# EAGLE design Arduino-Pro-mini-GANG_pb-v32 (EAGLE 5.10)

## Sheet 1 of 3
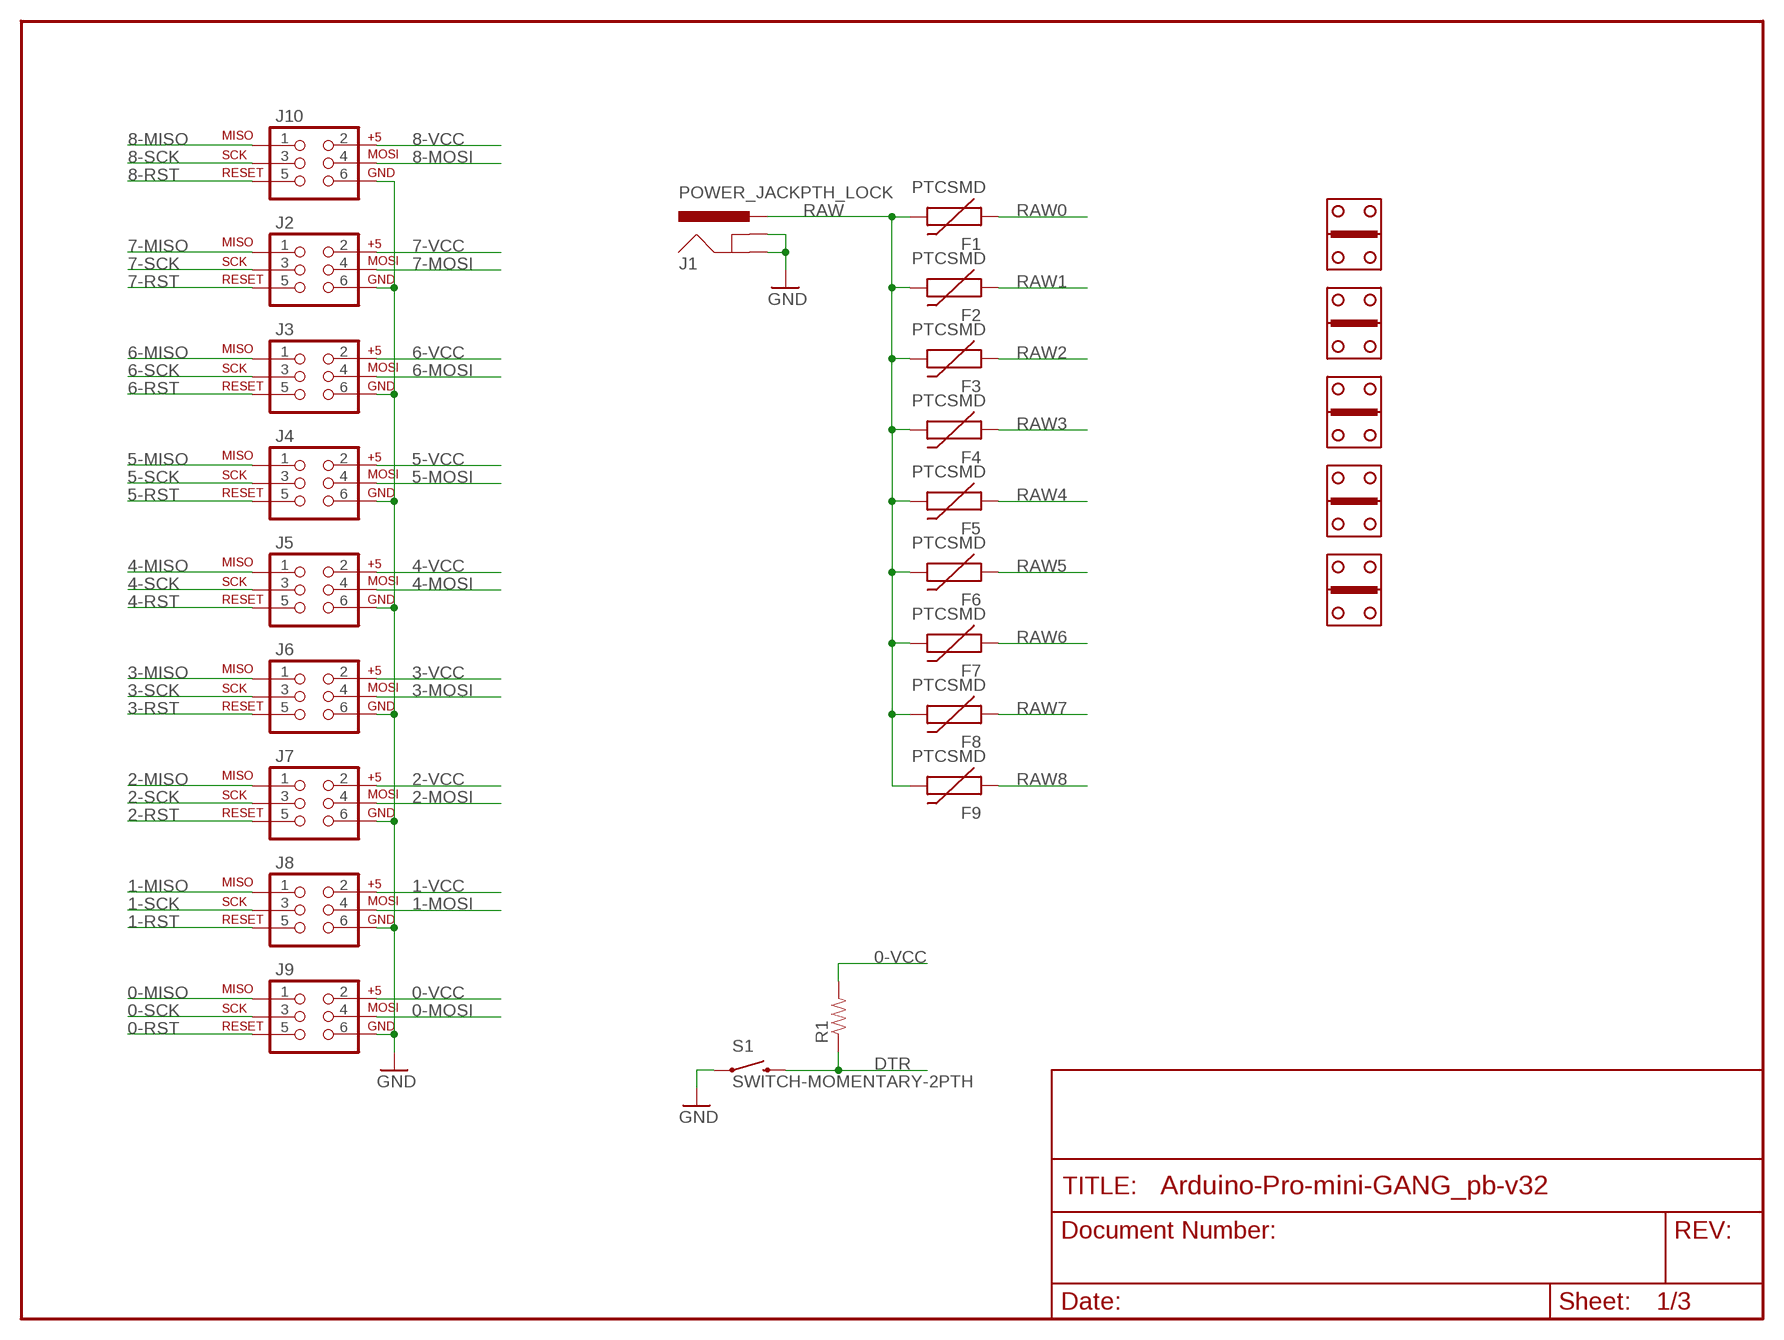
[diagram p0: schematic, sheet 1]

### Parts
F1  PTCSMD  [PTC-1206]
F2  PTCSMD  [PTC-1206]
F3  PTCSMD  [PTC-1206]
F4  PTCSMD  [PTC-1206]
F5  PTCSMD  [PTC-1206]
F6  PTCSMD  [PTC-1206]
F7  PTCSMD  [PTC-1206]
F8  PTCSMD  [PTC-1206]
F9  PTCSMD  [PTC-1206]
J1  POWER_JACKPTH_LOCK  [POWER_JACK_PTH_LOCK]
J2  AVR_SPI_PRG_62X3_LOCK  [2X3_LOCK]
J3  AVR_SPI_PRG_62X3_LOCK  [2X3_LOCK]
J4  AVR_SPI_PRG_62X3_LOCK  [2X3_LOCK]
J5  AVR_SPI_PRG_62X3_LOCK  [2X3_LOCK]
J6  AVR_SPI_PRG_62X3_LOCK  [2X3_LOCK]
J7  AVR_SPI_PRG_62X3_LOCK  [2X3_LOCK]
J8  AVR_SPI_PRG_62X3_LOCK  [2X3_LOCK]
J9  AVR_SPI_PRG_62X3_LOCK  [2X3_LOCK]
J10  AVR_SPI_PRG_62X3_LOCK  [2X3_LOCK]
R1  RESISTOR0603-RES  [0603-RES]
S1  SWITCH-MOMENTARY-2PTH  [TACTILE-PTH]
U$4  GOLD_HINDGESTANDARD  [GOLD_HINDGE]
U$5  GOLD_HINDGESTANDARD  [GOLD_HINDGE]
U$6  GOLD_HINDGESTANDARD  [GOLD_HINDGE]
U$7  GOLD_HINDGESTANDARD  [GOLD_HINDGE]
U$8  GOLD_HINDGESTANDARD  [GOLD_HINDGE]

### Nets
0-MISO: J9.1 ; also sheet 2
0-MOSI: J9.4 ; also sheet 2
0-RST: J9.5 ; also sheet 2
0-SCK: J9.3 ; also sheet 2
0-VCC: J9.2 R1.2 ; also sheet 2
1-MISO: J8.1 ; also sheet 2
1-MOSI: J8.4 ; also sheet 2
1-RST: J8.5 ; also sheet 2
1-SCK: J8.3 ; also sheet 2
1-VCC: J8.2 ; also sheet 2
2-MISO: J7.1 ; also sheet 2
2-MOSI: J7.4 ; also sheet 2
2-RST: J7.5 ; also sheet 2
2-SCK: J7.3 ; also sheet 2
2-VCC: J7.2 ; also sheet 2
3-MISO: J6.1 ; also sheet 2
3-MOSI: J6.4 ; also sheet 2
3-RST: J6.5 ; also sheet 2
3-SCK: J6.3 ; also sheet 2
3-VCC: J6.2 ; also sheet 2
4-MISO: J5.1 ; also sheet 2
4-MOSI: J5.4 ; also sheet 2
4-RST: J5.5 ; also sheet 2
4-SCK: J5.3 ; also sheet 2
4-VCC: J5.2 ; also sheet 2
5-MISO: J4.1 ; also sheet 2
5-MOSI: J4.4 ; also sheet 2
5-RST: J4.5 ; also sheet 2
5-SCK: J4.3 ; also sheet 2
5-VCC: J4.2 ; also sheet 2
6-MISO: J3.1 ; also sheet 2
6-MOSI: J3.4 ; also sheet 2
6-RST: J3.5 ; also sheet 2
6-SCK: J3.3 ; also sheet 2
6-VCC: J3.2 ; also sheet 2
7-MISO: J2.1 ; also sheet 2
7-MOSI: J2.4 ; also sheet 2
7-RST: J2.5 ; also sheet 2
7-SCK: J2.3 ; also sheet 2
7-VCC: J2.2 ; also sheet 2
8-MISO: J10.1 ; also sheet 2
8-MOSI: J10.4 ; also sheet 2
8-RST: J10.5 ; also sheet 2
8-SCK: J10.3 ; also sheet 2
8-VCC: J10.2 ; also sheet 2
DTR: R1.1 S1.3 ; also sheet 2
GND: J1.GND J1.GNDBREAK J2.6 J3.6 J4.6 J5.6 J6.6 J7.6 J8.6 J9.6 J10.6 S1.1 ; also sheet 2
RAW: F1.2 F2.2 F3.2 F4.2 F5.2 F6.2 F7.2 F8.2 F9.2 J1.PWR
RAW0: F1.1 ; also sheet 2
RAW1: F2.1 ; also sheet 2
RAW2: F3.1 ; also sheet 2
RAW3: F4.1 ; also sheet 2
RAW4: F5.1 ; also sheet 2
RAW5: F6.1 ; also sheet 2
RAW6: F7.1 ; also sheet 2
RAW7: F8.1 ; also sheet 2
RAW8: F9.1 ; also sheet 2

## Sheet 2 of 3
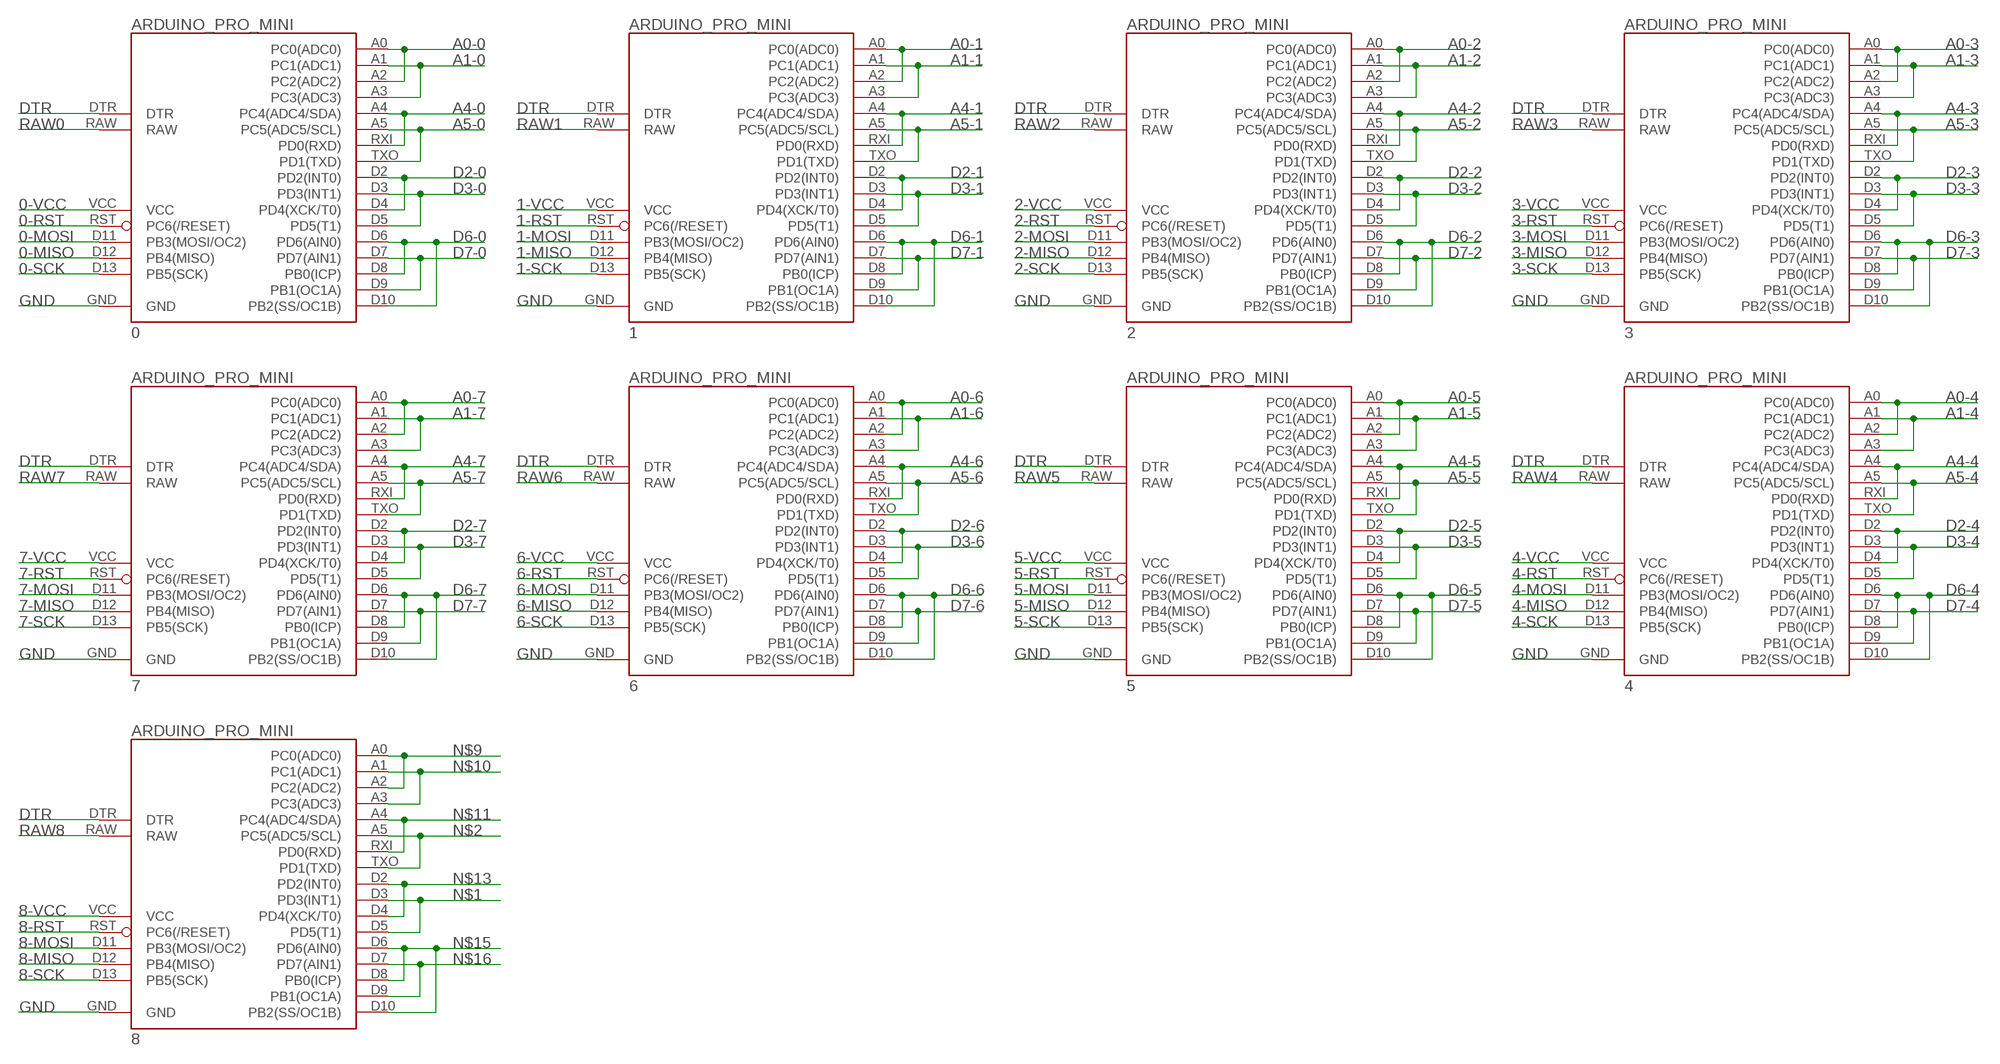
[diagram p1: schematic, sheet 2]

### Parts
0  ARDUINO_PRO_MINI  [ARDUINO_PRO_MINI]
1  ARDUINO_PRO_MINI  [ARDUINO_PRO_MINI]
2  ARDUINO_PRO_MINI  [ARDUINO_PRO_MINI]
3  ARDUINO_PRO_MINI  [ARDUINO_PRO_MINI]
4  ARDUINO_PRO_MINI  [ARDUINO_PRO_MINI]
5  ARDUINO_PRO_MINI  [ARDUINO_PRO_MINI]
6  ARDUINO_PRO_MINI  [ARDUINO_PRO_MINI]
7  ARDUINO_PRO_MINI  [ARDUINO_PRO_MINI]
8  ARDUINO_PRO_MINI  [ARDUINO_PRO_MINI]

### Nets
0-MISO: 0.D12(PB4(MISO)) ; also sheet 1
0-MOSI: 0.D11(PB3(MOSI/OC2)) ; also sheet 1
0-RST: 0.RST(PC6(/RESET)) ; also sheet 1
0-SCK: 0.D13(PB5(SCK)) ; also sheet 1
0-VCC: 0.VCC ; also sheet 1
1-MISO: 1.D12(PB4(MISO)) ; also sheet 1
1-MOSI: 1.D11(PB3(MOSI/OC2)) ; also sheet 1
1-RST: 1.RST(PC6(/RESET)) ; also sheet 1
1-SCK: 1.D13(PB5(SCK)) ; also sheet 1
1-VCC: 1.VCC ; also sheet 1
2-MISO: 2.D12(PB4(MISO)) ; also sheet 1
2-MOSI: 2.D11(PB3(MOSI/OC2)) ; also sheet 1
2-RST: 2.RST(PC6(/RESET)) ; also sheet 1
2-SCK: 2.D13(PB5(SCK)) ; also sheet 1
2-VCC: 2.VCC ; also sheet 1
3-MISO: 3.D12(PB4(MISO)) ; also sheet 1
3-MOSI: 3.D11(PB3(MOSI/OC2)) ; also sheet 1
3-RST: 3.RST(PC6(/RESET)) ; also sheet 1
3-SCK: 3.D13(PB5(SCK)) ; also sheet 1
3-VCC: 3.VCC ; also sheet 1
4-MISO: 4.D12(PB4(MISO)) ; also sheet 1
4-MOSI: 4.D11(PB3(MOSI/OC2)) ; also sheet 1
4-RST: 4.RST(PC6(/RESET)) ; also sheet 1
4-SCK: 4.D13(PB5(SCK)) ; also sheet 1
4-VCC: 4.VCC ; also sheet 1
5-MISO: 5.D12(PB4(MISO)) ; also sheet 1
5-MOSI: 5.D11(PB3(MOSI/OC2)) ; also sheet 1
5-RST: 5.RST(PC6(/RESET)) ; also sheet 1
5-SCK: 5.D13(PB5(SCK)) ; also sheet 1
5-VCC: 5.VCC ; also sheet 1
6-MISO: 6.D12(PB4(MISO)) ; also sheet 1
6-MOSI: 6.D11(PB3(MOSI/OC2)) ; also sheet 1
6-RST: 6.RST(PC6(/RESET)) ; also sheet 1
6-SCK: 6.D13(PB5(SCK)) ; also sheet 1
6-VCC: 6.VCC ; also sheet 1
7-MISO: 7.D12(PB4(MISO)) ; also sheet 1
7-MOSI: 7.D11(PB3(MOSI/OC2)) ; also sheet 1
7-RST: 7.RST(PC6(/RESET)) ; also sheet 1
7-SCK: 7.D13(PB5(SCK)) ; also sheet 1
7-VCC: 7.VCC ; also sheet 1
8-MISO: 8.D12(PB4(MISO)) ; also sheet 1
8-MOSI: 8.D11(PB3(MOSI/OC2)) ; also sheet 1
8-RST: 8.RST(PC6(/RESET)) ; also sheet 1
8-SCK: 8.D13(PB5(SCK)) ; also sheet 1
8-VCC: 8.VCC ; also sheet 1
A0-0: 0.A0(PC0(ADC0)) 0.A2(PC2(ADC2))
A0-1: 1.A0(PC0(ADC0)) 1.A2(PC2(ADC2))
A0-2: 2.A0(PC0(ADC0)) 2.A2(PC2(ADC2))
A0-3: 3.A0(PC0(ADC0)) 3.A2(PC2(ADC2))
A0-4: 4.A0(PC0(ADC0)) 4.A2(PC2(ADC2))
A0-5: 5.A0(PC0(ADC0)) 5.A2(PC2(ADC2))
A0-6: 6.A0(PC0(ADC0)) 6.A2(PC2(ADC2))
A0-7: 7.A0(PC0(ADC0)) 7.A2(PC2(ADC2))
A1-0: 0.A1(PC1(ADC1)) 0.A3(PC3(ADC3))
A1-1: 1.A1(PC1(ADC1)) 1.A3(PC3(ADC3))
A1-2: 2.A1(PC1(ADC1)) 2.A3(PC3(ADC3))
A1-3: 3.A1(PC1(ADC1)) 3.A3(PC3(ADC3))
A1-4: 4.A1(PC1(ADC1)) 4.A3(PC3(ADC3))
A1-5: 5.A1(PC1(ADC1)) 5.A3(PC3(ADC3))
A1-6: 6.A1(PC1(ADC1)) 6.A3(PC3(ADC3))
A1-7: 7.A1(PC1(ADC1)) 7.A3(PC3(ADC3))
A4-0: 0.A4(PC4(ADC4/SDA)) 0.RXI(PD0(RXD))
A4-1: 1.A4(PC4(ADC4/SDA)) 1.RXI(PD0(RXD))
A4-2: 2.A4(PC4(ADC4/SDA)) 2.RXI(PD0(RXD))
A4-3: 3.A4(PC4(ADC4/SDA)) 3.RXI(PD0(RXD))
A4-4: 4.A4(PC4(ADC4/SDA)) 4.RXI(PD0(RXD))
A4-5: 5.A4(PC4(ADC4/SDA)) 5.RXI(PD0(RXD))
A4-6: 6.A4(PC4(ADC4/SDA)) 6.RXI(PD0(RXD))
A4-7: 7.A4(PC4(ADC4/SDA)) 7.RXI(PD0(RXD))
A5-0: 0.A5(PC5(ADC5/SCL)) 0.TXO(PD1(TXD))
A5-1: 1.A5(PC5(ADC5/SCL)) 1.TXO(PD1(TXD))
A5-2: 2.A5(PC5(ADC5/SCL)) 2.TXO(PD1(TXD))
A5-3: 3.A5(PC5(ADC5/SCL)) 3.TXO(PD1(TXD))
A5-4: 4.A5(PC5(ADC5/SCL)) 4.TXO(PD1(TXD))
A5-5: 5.A5(PC5(ADC5/SCL)) 5.TXO(PD1(TXD))
A5-6: 6.A5(PC5(ADC5/SCL)) 6.TXO(PD1(TXD))
A5-7: 7.A5(PC5(ADC5/SCL)) 7.TXO(PD1(TXD))
D2-0: 0.D2(PD2(INT0)) 0.D4(PD4(XCK/T0))
D2-1: 1.D2(PD2(INT0)) 1.D4(PD4(XCK/T0))
D2-2: 2.D2(PD2(INT0)) 2.D4(PD4(XCK/T0))
D2-3: 3.D2(PD2(INT0)) 3.D4(PD4(XCK/T0))
D2-4: 4.D2(PD2(INT0)) 4.D4(PD4(XCK/T0))
D2-5: 5.D2(PD2(INT0)) 5.D4(PD4(XCK/T0))
D2-6: 6.D2(PD2(INT0)) 6.D4(PD4(XCK/T0))
D2-7: 7.D2(PD2(INT0)) 7.D4(PD4(XCK/T0))
D3-0: 0.D3(PD3(INT1)) 0.D5(PD5(T1))
D3-1: 1.D3(PD3(INT1)) 1.D5(PD5(T1))
D3-2: 2.D3(PD3(INT1)) 2.D5(PD5(T1))
D3-3: 3.D3(PD3(INT1)) 3.D5(PD5(T1))
D3-4: 4.D3(PD3(INT1)) 4.D5(PD5(T1))
D3-5: 5.D3(PD3(INT1)) 5.D5(PD5(T1))
D3-6: 6.D3(PD3(INT1)) 6.D5(PD5(T1))
D3-7: 7.D3(PD3(INT1)) 7.D5(PD5(T1))
D6-0: 0.D6(PD6(AIN0)) 0.D8(PB0(ICP)) 0.D10(PB2(SS/OC1B))
D6-1: 1.D6(PD6(AIN0)) 1.D8(PB0(ICP)) 1.D10(PB2(SS/OC1B))
D6-2: 2.D6(PD6(AIN0)) 2.D8(PB0(ICP)) 2.D10(PB2(SS/OC1B))
D6-3: 3.D6(PD6(AIN0)) 3.D8(PB0(ICP)) 3.D10(PB2(SS/OC1B))
D6-4: 4.D6(PD6(AIN0)) 4.D8(PB0(ICP)) 4.D10(PB2(SS/OC1B))
D6-5: 5.D6(PD6(AIN0)) 5.D8(PB0(ICP)) 5.D10(PB2(SS/OC1B))
D6-6: 6.D6(PD6(AIN0)) 6.D8(PB0(ICP)) 6.D10(PB2(SS/OC1B))
D6-7: 7.D6(PD6(AIN0)) 7.D8(PB0(ICP)) 7.D10(PB2(SS/OC1B))
D7-0: 0.D7(PD7(AIN1)) 0.D9(PB1(OC1A))
D7-1: 1.D7(PD7(AIN1)) 1.D9(PB1(OC1A))
D7-2: 2.D7(PD7(AIN1)) 2.D9(PB1(OC1A))
D7-3: 3.D7(PD7(AIN1)) 3.D9(PB1(OC1A))
D7-4: 4.D7(PD7(AIN1)) 4.D9(PB1(OC1A))
D7-5: 5.D7(PD7(AIN1)) 5.D9(PB1(OC1A))
D7-6: 6.D7(PD7(AIN1)) 6.D9(PB1(OC1A))
D7-7: 7.D7(PD7(AIN1)) 7.D9(PB1(OC1A))
DTR: 0.DTR 1.DTR 2.DTR 3.DTR 4.DTR 5.DTR 6.DTR 7.DTR 8.DTR ; also sheet 1
GND: 0.GND 1.GND 2.GND 3.GND 4.GND 5.GND 6.GND 7.GND 8.GND ; also sheet 1
N$1: 8.D3(PD3(INT1)) 8.D5(PD5(T1))
N$2: 8.A5(PC5(ADC5/SCL)) 8.TXO(PD1(TXD))
N$9: 8.A0(PC0(ADC0)) 8.A2(PC2(ADC2))
N$10: 8.A1(PC1(ADC1)) 8.A3(PC3(ADC3))
N$11: 8.A4(PC4(ADC4/SDA)) 8.RXI(PD0(RXD))
N$13: 8.D2(PD2(INT0)) 8.D4(PD4(XCK/T0))
N$15: 8.D6(PD6(AIN0)) 8.D8(PB0(ICP)) 8.D10(PB2(SS/OC1B))
N$16: 8.D7(PD7(AIN1)) 8.D9(PB1(OC1A))
RAW0: 0.RAW ; also sheet 1
RAW1: 1.RAW ; also sheet 1
RAW2: 2.RAW ; also sheet 1
RAW3: 3.RAW ; also sheet 1
RAW4: 4.RAW ; also sheet 1
RAW5: 5.RAW ; also sheet 1
RAW6: 6.RAW ; also sheet 1
RAW7: 7.RAW ; also sheet 1
RAW8: 8.RAW ; also sheet 1

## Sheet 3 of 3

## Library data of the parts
0 1-8 = unclepetes:ARDUINO_PRO_MINI
F1-F9 = SparkFun:PTC: Resettable Fuse PTC
J1 = SparkFun:POWER_JACK: Power Jack This is the standard 5.5mm barrel jack for power. The PTH is the most common, proven, reliable, footprint. All others are experimental. The Slot footprint only works if the mill layer is transmitted to the PCB fab house so be warned. Spark Fun Electronics SKU : PRT-00119. Mating wall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
J2-J10 = Testing:AVR_SPI_PRG_6: AVR ISP 6 Pin This is the reduced ISP connector for AVR programming. Common on Arduino. This footprint will take up less PCB space and can be used with a 10-pin to 6-pin adapter such as SKU: BOB-08508
R1 = SparkFun:RESISTOR: Resistor
S1 = SparkFun:SWITCH-MOMENTARY-2
U$4-U$8 = Testing:GOLD_HINDGE

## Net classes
0 Default: width 0.203 mm
1 VCC: width 0.305 mm

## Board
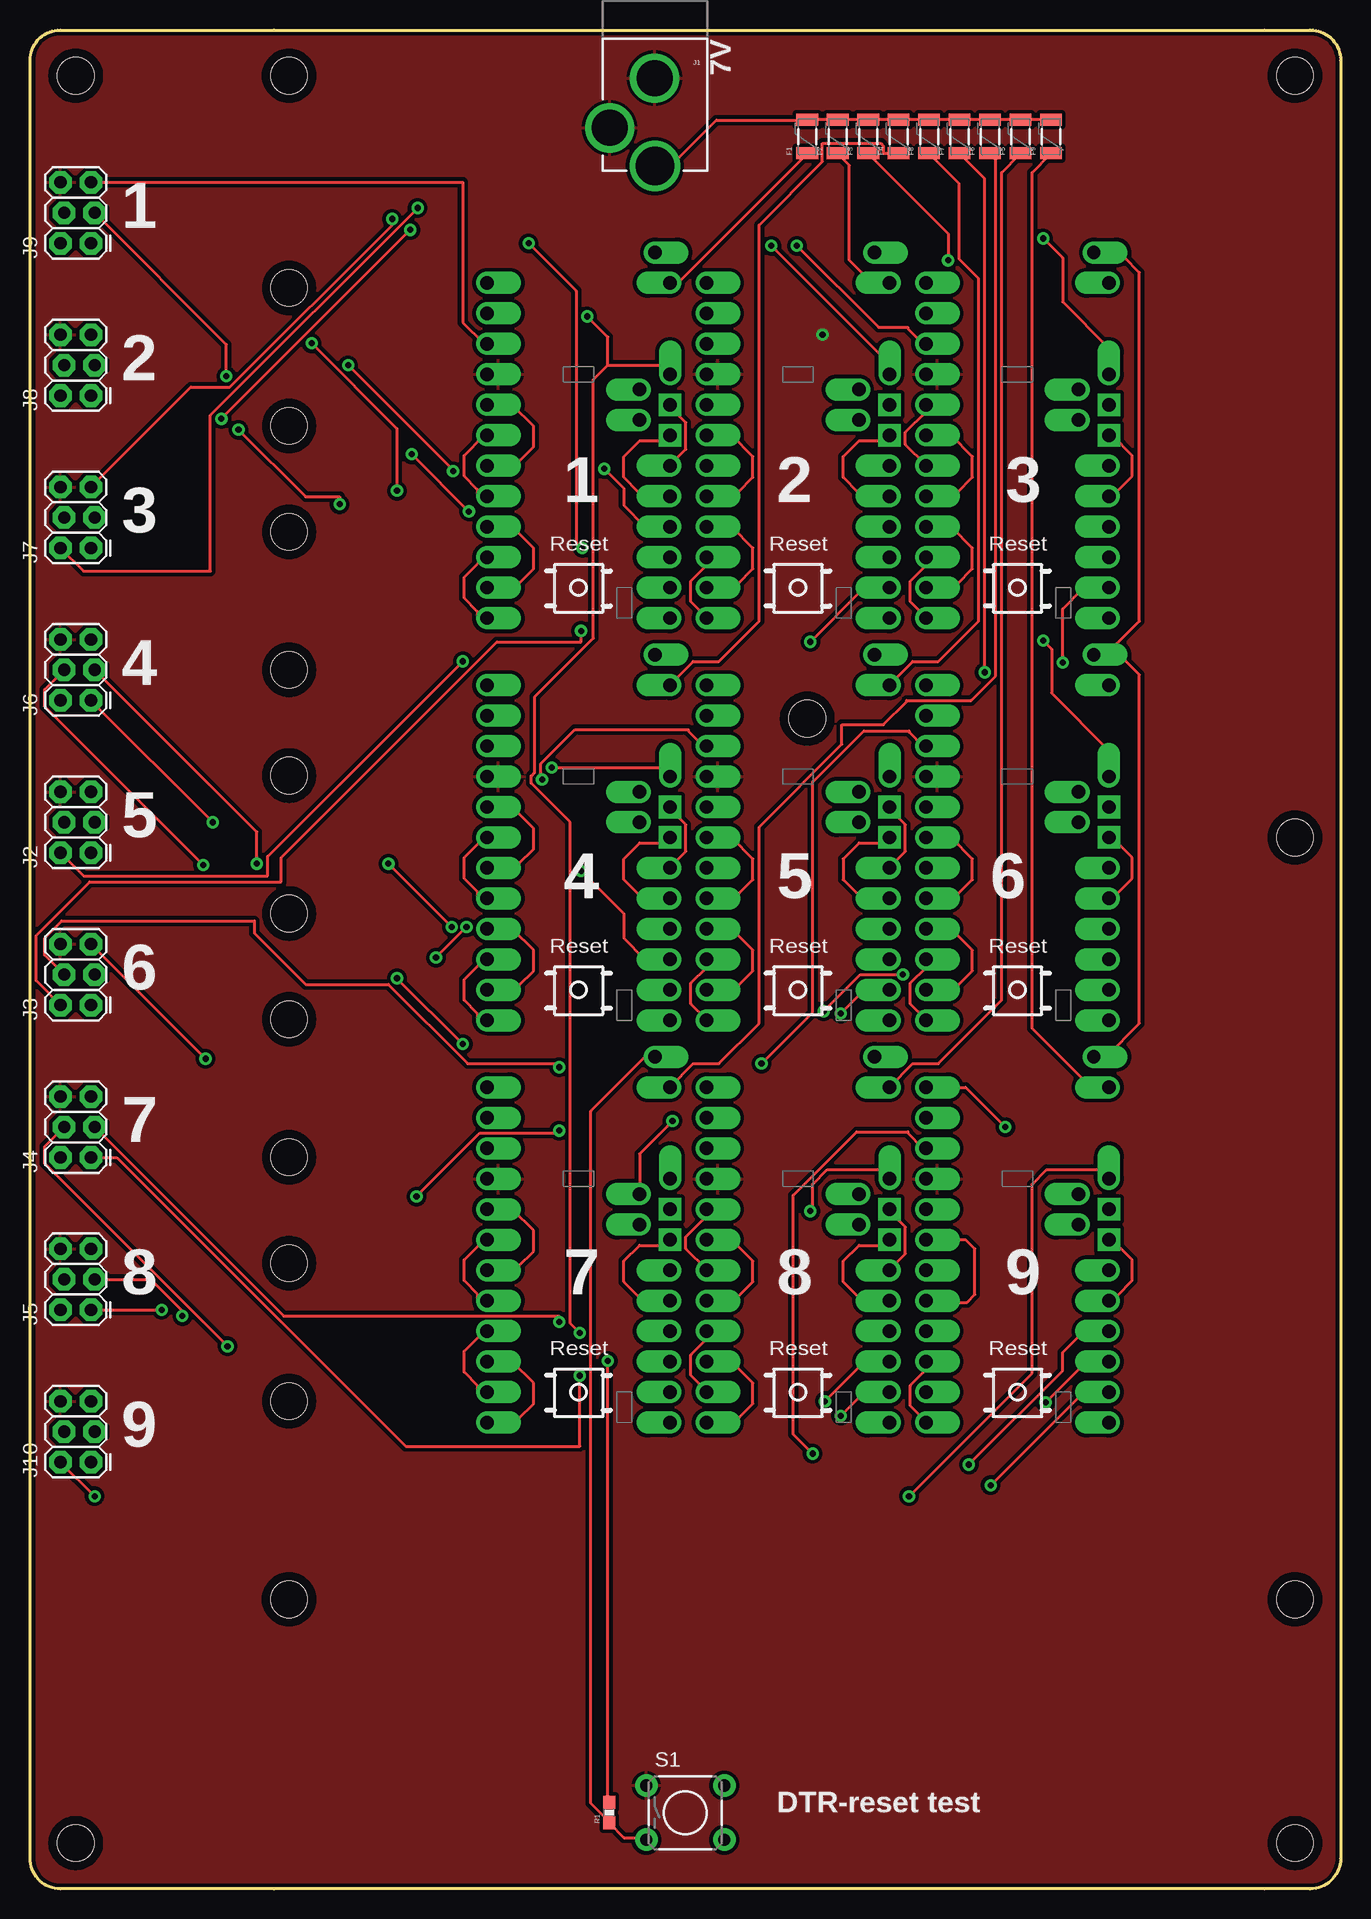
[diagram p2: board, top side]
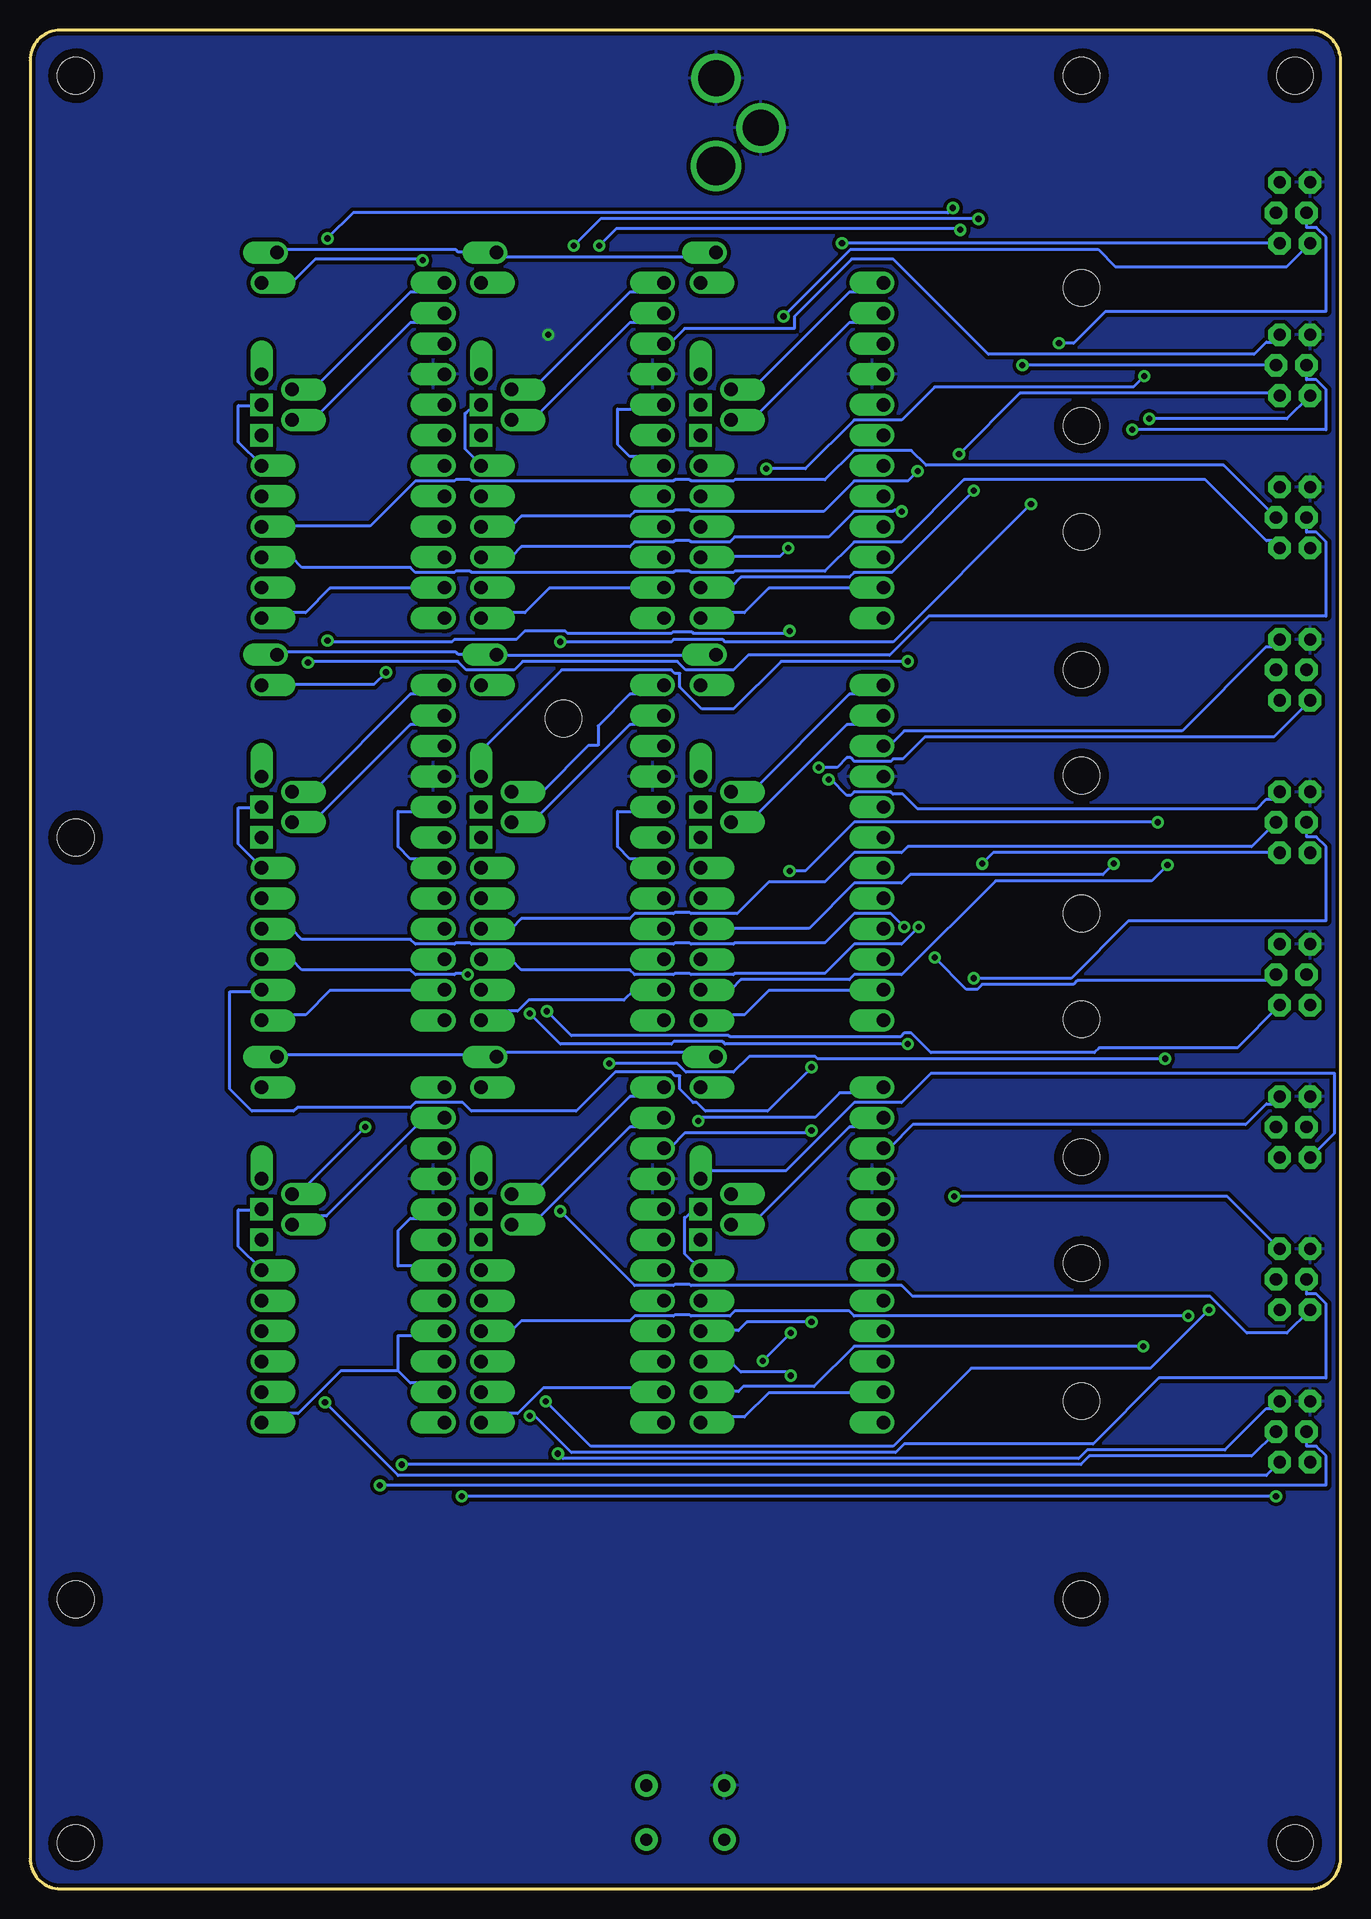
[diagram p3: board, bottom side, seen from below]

Size 109.22 x 154.94 mm. Coordinates in mm from the lower left corner, seen from the top.
Outline: 20.32,154.94 106.68,154.94 arc-90 109.22,152.4 109.22,2.54 arc-90 106.68,0 20.32,0
Outline: 102.87,154.94 2.54,154.94 arc90 0,152.4 0,2.54 arc90 2.54,0 102.87,0
Copper layers (1*16): Top 0.035mm / dielectric 1.5mm / Bottom 0.035mm
Design rules "SparkFun *": minimum track width 10mil, minimum drill 20mil, track to track 8mil, track to pad 8mil, pad to pad 8mil, via to via 8mil, smd to smd 8mil, copper to edge 10mil, drill to drill 8mil, minimum pad ring 12mil, minimum via ring 10mil, stop-mask expansion 4mil, vias tented up to drill 20mil, thermal gap 10mil

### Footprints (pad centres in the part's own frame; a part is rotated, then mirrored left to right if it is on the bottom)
ARDUINO_PRO_MINI = drill 1.118 pad 1.88 offset: A0 16.51,11.43; A1 16.51,13.97; A4 13.97,17.78; A5 13.97,20.32; D2 1.27,19.05; D3 1.27,16.51; D4 1.27,13.97; D5 1.27,11.43; D6 1.27,8.89; D7 1.27,6.35; D8 1.27,3.81; D9 1.27,1.27; D10 16.51,1.27; D11 16.51,3.81; D12 16.51,6.35; D13 16.51,8.89; DTR 15.24,31.75; GND 1.27,21.59; RAW 16.51,29.21; RST 1.27,24.13; RXI 1.27,26.67; TXO 1.27,29.21; VCC 16.51,21.59 | drill 1.118 pad 1.88 square: A2 16.51,16.51; A3 16.51,19.05
PTC-1206 = smd 1 x 1.8: 1 -1.4,0; 2 1.4,0
POWER_JACK_PTH_LOCK = drill 2.997 pad 4.115 round: GND 0.025,6.557; GNDBREAK 3.762,10.7 | drill 3.2 pad 4.115 round: PWR 0,13.878
2X3_LOCK = drill 1.016 pad 1.88 octagon: 1 0,0; 2 0,2.54; 3 2.54,-0.305; 4 2.54,2.235; 5 5.08,0; 6 5.08,2.54
0603-RES = smd 1.1 x 1: 1 -0.85,0; 2 0.85,0
TACTILE-PTH = drill 1.016 pad 1.88 round: 1 -3.251,2.261; 2 3.251,2.261; 3 -3.251,-2.261; 4 3.251,-2.261
STAND-OFF-TIGHT = hole 3.048: 0,0
GOLD_HINDGE = hole 3.048: 3.81,3.823; 3.81,15.324

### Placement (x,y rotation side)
0  36.83,104.65 0 top
1  55.12,104.65 0 top
2  73.41,104.65 0 top
3  36.83,71.12 0 top
4  55.12,37.59 0 top
5  36.83,37.59 0 top
6  73.41,71.12 0 top
7  55.12,71.12 0 top
8  73.41,37.59 0 top
F1  64.77,146.05 90 top
F2  67.31,146.05 90 top
F3  69.85,146.05 90 top
F4  72.39,146.05 90 top
F5  82.55,146.05 90 top
F6  80.01,146.05 90 top
F7  77.47,146.05 90 top
F8  74.93,146.05 90 top
F9  85.09,146.05 90 top
J1  52.07,157.48 180 top
J2  5.08,86.36 90 top
J3  5.08,73.66 90 top
J4  5.08,60.96 90 top
J5  5.08,48.26 90 top
J6  5.08,99.06 90 top
J7  5.08,111.76 90 top
J8  5.08,124.46 90 top
J9  5.08,137.16 90 top
J10  5.08,35.56 90 top
R1  48.26,6.35 90 top
S1  54.61,6.35 0 top
U$1  [STAND-OFF-TIGHT]  64.77,97.54 0 top
U$2  [STAND-OFF-TIGHT]  3.81,151.13 0 top
U$3  [STAND-OFF-TIGHT]  3.81,3.81 0 top
U$4  17.78,118.11 0 top
U$5  17.78,97.79 0 top
U$6  17.78,77.47 0 top
U$7  17.78,57.15 0 top
U$8  17.78,36.83 0 top
U$9  [STAND-OFF-TIGHT]  105.41,87.63 0 top
U$31  [STAND-OFF-TIGHT]  21.59,151.13 0 top
U$32  [STAND-OFF-TIGHT]  105.41,151.13 0 top
U$33  [STAND-OFF-TIGHT]  105.41,3.81 0 top
U$35  [STAND-OFF-TIGHT]  21.59,24.13 0 top
U$36  [STAND-OFF-TIGHT]  105.41,24.13 0 top

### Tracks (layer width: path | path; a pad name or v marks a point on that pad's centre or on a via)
0-MISO  (via drill 0.51)
  Top 0.254: v41.55,137.16 45.52,133.2 45.52,112.27 v46.02,111.76
  Bottom 0.254: J9.1 v41.55,137.16 | v46.02,111.76 46.74,111.05 53.34,111.05 0.D12
0-MOSI  (via drill 0.51)
  Top 0.254: v23.47,128.83 30.58,121.72 v30.58,116.53
  Bottom 0.254: J9.4 2.85,138.48 2.03,138.48 1.22,137.67 1.22,131.47 19.61,131.47 22.25,128.83 v23.47,128.83 | v30.58,116.53 37.39,109.73 40.54,109.73 40.95,109.32 49.99,109.32 50.8,108.51 53.34,108.51 0.D11
0-RST
  Top 0.254: J9.5 36.07,142.24 36.07,130.56 37.8,128.83 38.1,128.83 0.RST
0-SCK  (via drill 0.51)
  Top 0.254: J9.3 16.36,128.73 v16.36,126.09 | v47.85,118.36 49.48,116.74 49.48,115.32 51.21,113.59 53.34,113.59 0.D13
  Bottom 0.254: v16.36,126.09 17.27,125.17 33.83,125.17 36.58,122.43 40.54,122.43 44.6,118.36 v47.85,118.36
0-VCC  (via drill 0.51)
  Top 0.254: v48.16,43.99 48.16,7.32 48.26,7.21 R1.2 | v45.82,46.33 45.01,47.14 45.01,88.9 41.76,92.15 41.76,92.76 42.06,93.07 42.06,99.37 46.94,104.24 46.94,125.78 48.16,127 | 48.16,127 53.34,127 0.VCC | v46.43,131.06 48.16,129.34 48.16,127
  Bottom 0.254: v48.16,43.99 v45.82,46.33 | J9.2 4.47,135.23 18.8,135.23 20.22,136.65 40.84,136.65 v46.43,131.06
1-MISO  (via drill 0.51)
  Top 0.254: v31.8,119.58 v36.58,114.81
  Bottom 0.254: J8.1 5.28,124.66 26.72,124.66 v31.8,119.58 | v36.58,114.81 36.68,114.91 37.19,114.91 37.29,114.81 40.54,114.81 42.67,112.67 50.49,112.67 50.9,112.27 54.15,112.27 54.25,112.37 55.47,112.37 55.58,112.27 58.83,112.27 59.23,111.86 68.28,111.86 69.09,111.05 71.63,111.05 1.D12
1-MOSI  (via drill 0.51)
  Top 0.254: v17.37,121.62 22.96,116.03 25.81,116.03 v25.81,115.42 | v65.02,103.94 69.49,108.41 71.63,108.41 1.D11
  Bottom 0.254: J8.4 2.85,125.78 2.03,125.78 1.22,124.97 1.22,121.62 v17.37,121.62 | v25.81,115.42 37.29,103.94 51.31,103.94 51.51,104.14 55.58,104.14 55.78,103.94 v65.02,103.94
1-RST
  Bottom 0.254: J8.5 5.69,128.93 6.2,128.93 7.21,127.91 29.36,127.91 37.29,135.84 40.74,135.84 45.52,131.06 45.52,130.05 54.66,130.05 55.88,128.83 56.39,128.83 1.RST
1-SCK  (via drill 0.51)
  Top 0.254: v26.52,127 35.26,118.26 v35.26,118.16
  Bottom 0.254: J8.3 v26.52,127 | v35.26,118.16 36.07,117.35 40.54,117.35 43.08,114.81 54.15,114.81 54.25,114.91 55.47,114.91 55.58,114.81 58.83,114.81 59.23,114.4 68.28,114.4 69.09,113.59 71.63,113.59 1.D13
1-VCC  (via drill 0.51)
  Top 0.254: v15.95,122.53 v31.7,138.28 | v61.77,136.96 71.63,127.1 1.VCC
  Bottom 0.254: J8.2 4.47,122.53 v15.95,122.53 | v31.7,138.28 31.8,138.38 60.35,138.38 v61.77,136.96
2-MISO
  Bottom 0.254: J7.1 5.69,112.37 6.2,112.37 11.28,117.45 31.39,117.45 36.58,112.27 40.54,112.27 42.98,109.83 50.49,109.83 50.6,109.73 54.15,109.73 54.25,109.83 55.47,109.83 55.58,109.73 72.44,109.73 72.54,109.83 73.76,109.83 73.86,109.73 77.11,109.73 77.52,110.13 86.56,110.13 87.38,110.95 89.92,110.95 2.D12
2-MOSI  (via drill 0.51)
  Top 0.254: v86.06,102.21 86.06,106.68 87.78,108.41 89.92,108.41 2.D11
  Bottom 0.254: J7.4 2.85,113.08 2.03,113.08 1.22,112.27 1.22,106.07 34.34,106.07 37.59,102.82 49.38,102.82 50.6,101.6 54.56,101.6 55.27,102.31 68.17,102.31 68.89,101.6 72.85,101.6 73.56,102.31 85.95,102.31 v86.06,102.21
2-RST  (via drill 0.51)
  Top 0.254: J7.5 13.41,125.17 16.66,125.17 30.18,138.68 v30.18,139.19 | v63.91,136.96 70.71,130.15 73.15,130.15 73.15,130.05 74.37,128.83 74.68,128.83 2.RST
  Bottom 0.254: v30.18,139.19 61.67,139.19 v63.91,136.96
2-SCK
  Bottom 0.254: J7.3 9.75,118.67 34.54,118.67 35.76,119.89 40.54,119.89 42.98,117.45 50.49,117.45 50.6,117.35 54.15,117.35 54.25,117.45 55.47,117.45 55.58,117.35 72.44,117.35 72.54,117.45 73.76,117.45 73.86,117.35 77.11,117.35 80.87,113.59 89.92,113.59 2.D13
2-VCC  (via drill 0.51)
  Top 0.254: J7.2 4.47,109.83 15.04,109.83 15.04,122.83 v32.31,140.11 | v84.43,137.57 86.06,135.94 86.06,132.28 89.92,128.42 2.VCC
  Bottom 0.254: v32.31,140.11 32.72,139.7 82.3,139.7 v84.43,137.57
3-MISO  (via drill 0.51)
  Top 0.254: J6.1 v15.24,88.9 | v45.92,84.84 49.48,81.28 49.48,79.25 51.21,77.52 53.34,77.52 3.D12
  Bottom 0.254: v15.24,88.9 40.54,88.9 44.6,84.84 v45.92,84.84
3-MOSI  (via drill 0.51)
  Top 0.254: J6.4 1.22,99.97 1.22,98.55 v14.43,85.34
  Bottom 0.254: v14.43,85.34 15.75,84.02 28.75,84.02 36.58,76.2 40.54,76.2 40.95,75.79 49.99,75.79 50.8,74.98 53.34,74.98 3.D11
3-RST
  Bottom 0.254: J6.5 5.69,103.53 6.2,103.53 13.21,96.52 36.37,96.52 37.59,95.3 38.1,95.3 3.RST
3-SCK  (via drill 0.51)
  Top 0.254: J6.3 18.9,88.09 v18.9,85.45
  Bottom 0.254: v18.9,85.45 19.81,84.53 35.87,84.53 36.58,83.82 40.54,83.82 44.3,80.06 53.34,80.06 3.D13
3-VCC  (via drill 0.51)
  Top 0.254: v43.48,93.47 53.34,93.47 3.VCC
  Bottom 0.254: J6.2 5.59,96.01 34.65,96.01 36.47,94.18 37.29,94.18 37.49,93.98 40.54,93.98 40.84,94.28 41.15,94.28 41.96,93.47 v43.48,93.47
4-MISO  (via drill 0.51)
  Top 0.254: J5.1 v10.97,48.26 | v66.24,40.64 69.49,43.89 71.63,43.89 4.D12
  Bottom 0.254: v10.97,48.26 15.85,43.38 30.79,43.38 37.29,36.88 62.48,36.88 v66.24,40.64
4-MOSI  (via drill 0.51)
  Top 0.254: v67.56,39.42 69.49,41.35 71.63,41.35 4.D11
  Bottom 0.254: J5.4 2.85,49.58 2.03,49.58 1.22,48.77 1.22,42.57 15.14,42.57 20.62,37.08 36.37,37.08 37.08,36.37 64.11,36.37 67.16,39.42 v67.56,39.42
4-RST  (via drill 0.51)
  Top 0.254: v32.21,57.71 37.49,62.99 44.09,62.99 v44.09,63.2
  Bottom 0.254: J5.5 9.45,57.71 v32.21,57.71 | v44.09,63.2 44.3,62.99 54.66,62.99 55.88,61.77 56.39,61.77 4.RST
4-SCK  (via drill 0.51)
  Top 0.254: J5.3 10.16,50.8 10.16,50.7 12.7,48.16 v12.7,47.75
  Bottom 0.254: v12.7,47.75 40.54,47.75 40.95,48.16 50.49,48.16 50.9,47.75 54.15,47.75 54.25,47.85 55.47,47.85 55.58,47.75 58.83,47.75 59.23,47.35 68.28,47.35 69.09,46.53 71.63,46.53 4.D13
4-VCC  (via drill 0.51)
  Top 0.254: v65.02,56.49 65.23,56.69 65.23,58.73 66.45,59.94 71.63,59.94 4.VCC
  Bottom 0.254: J5.2 4.47,46.33 7.82,46.33 10.87,49.38 35.66,49.38 36.58,50.29 54.15,50.29 54.25,50.39 55.47,50.39 55.58,50.29 58.83,50.29 v65.02,56.49
5-MISO  (via drill 0.51)
  Top 0.254: J4.1 7.21,60.96 31.29,36.88 45.82,36.88 v45.82,42.77
  Bottom 0.254: v45.82,42.77 46.13,43.08 49.99,43.08 50.8,43.89 53.34,43.89 5.D12
5-MOSI  (via drill 0.51)
  Top 0.254: J4.4 1.22,61.87 1.22,60.45 v16.46,45.21
  Bottom 0.254: v16.46,45.21 40.54,45.21 43.89,41.86 49.78,41.86 50.19,41.45 53.34,41.45 5.D11
5-RST
  Bottom 0.254: J4.5 5.69,65.43 6.2,65.43 7.92,63.7 35.66,63.7 37.59,61.77 38.1,61.77 5.RST
5-SCK  (via drill 0.51)
  Top 0.254: J4.3 21.13,47.75 44.09,47.75 v44.09,47.24
  Bottom 0.254: v44.09,47.24 49.48,47.24 50.19,46.53 53.34,46.53 5.D13
5-VCC
  Bottom 0.254: J4.2 0.51,62.99 0.51,67.97 34.14,67.97 36.58,65.53 40.54,65.53 46.23,59.84 52.73,59.84 53.34,59.23 5.VCC
6-MISO  (via drill 0.51)
  Top 0.254: v66.14,73.15 69.19,76.2 v72.75,76.2
  Bottom 0.254: J3.1 8.64,70.1 20.12,70.1 20.52,69.7 34.14,69.7 35.76,71.32 36.37,71.32 36.68,71.02 50.9,71.02 51,71.12 64.11,71.12 v66.14,73.15 | v72.75,76.2 72.85,76.3 73.76,76.3 73.86,76.2 77.11,76.2 77.52,76.61 86.56,76.61 87.38,77.42 89.92,77.42 6.D12
6-MOSI  (via drill 0.51)
  Top 0.254: J3.4 1.22,77.83 1.22,79.25 2.64,80.67 18.69,80.67 18.69,79.65 22.96,75.39 29.87,75.39 36.47,68.78 44.09,68.78 v44.09,68.48
  Bottom 0.254: v44.09,68.48 47.75,64.82 52.93,64.82 53.65,65.53 53.95,65.53 55.07,66.65 55.07,67.77 55.47,67.77 55.78,68.07 60.45,68.07 63.7,64.82 72.44,64.82 73.15,65.53 77.11,65.53 77.52,65.13 86.97,65.13 87.27,64.82 90.73,64.82 92.56,66.65 92.56,74.78 90.02,74.78 89.92,74.88 6.D11
6-RST  (via drill 0.51)
  Top 0.254: v14.63,69.19 J3.5 | v60.96,68.78 65.23,73.05 65.23,92.25 69.49,96.52 73.25,96.52 73.25,96.42 74.37,95.3 74.68,95.3 6.RST
  Bottom 0.254: v14.63,69.19 43.59,69.19 43.79,69.39 49.28,69.39 50.6,68.07 54.56,68.07 55.27,68.78 v60.96,68.78
6-SCK  (via drill 0.51)
  Top 0.254: v33.83,77.62 v36.37,80.16
  Bottom 0.254: J3.3 5.89,75.69 21.95,75.69 22.25,75.39 29.87,75.39 30.28,74.98 31.19,74.98 v33.83,77.62 | v36.37,80.16 37.49,81.28 40.54,81.28 42.98,78.84 50.49,78.84 50.6,78.74 54.15,78.74 54.25,78.84 55.47,78.84 55.58,78.74 72.44,78.74 72.54,78.84 73.76,78.84 73.86,78.74 77.11,78.74 77.52,79.15 86.56,79.15 87.38,79.96 89.92,79.96 6.D13
6-VCC  (via drill 0.51)
  Top 0.254: J3.2 0.51,75.69 0.51,79.45 4.98,83.92 20.93,83.92 20.93,85.95 38.91,103.94 45.92,103.94 v45.92,104.85 | v84.43,104.04 85.14,103.33 85.14,99.67 89.92,94.89 6.VCC
  Bottom 0.254: v45.92,104.85 46.13,104.65 53.95,104.65 54.05,104.75 55.68,104.75 55.78,104.65 64.41,104.65 64.62,104.85 67.97,104.85 68.68,104.14 73.86,104.14 74.07,103.94 84.33,103.94 v84.43,104.04
7-MISO  (via drill 0.51)
  Top 0.254: v29.87,85.45 v35.15,80.16
  Bottom 0.254: J2.1 28.96,86.36 v29.87,85.45 | v35.15,80.16 36.58,78.74 40.54,78.74 42.98,76.3 50.49,76.3 50.6,76.2 54.15,76.2 54.25,76.3 55.47,76.3 55.58,76.2 58.83,76.2 59.23,76.61 68.28,76.61 69.09,77.42 71.63,77.42 7.D12
7-MOSI  (via drill 0.51)
  Top 0.254: v30.58,75.9 v36.07,70.41 | v67.56,72.95 69.49,74.88 71.63,74.88 7.D11
  Bottom 0.254: J2.4 2.85,87.68 2.03,87.68 1.22,86.87 1.22,80.67 17.68,80.67 22.45,75.9 v30.58,75.9 | v36.07,70.41 51.31,70.41 51.51,70.61 55.58,70.61 55.78,70.41 65.02,70.41 v67.56,72.95
7-RST  (via drill 0.51)
  Top 0.254: v42.67,92.46 42.57,92.56 42.57,93.78 45.41,96.62 54.86,96.62 54.86,96.52 56.08,95.3 56.39,95.3 7.RST
  Bottom 0.254: J2.5 5.69,90.83 6.2,90.83 7.01,90.02 35.26,90.02 36.47,91.24 37.29,91.24 37.49,91.44 40.54,91.44 40.84,91.14 41.15,91.14 42.47,92.46 v42.67,92.46
7-SCK
  Bottom 0.254: J2.3 7.42,86.87 36.07,86.87 36.58,86.36 40.54,86.36 42.98,83.92 47.65,83.92 50.29,81.28 54.15,81.28 54.25,81.38 55.47,81.38 55.58,81.28 58.83,81.28 59.23,80.87 68.28,80.87 69.09,80.06 71.63,80.06 7.D13
7-VCC  (via drill 0.51)
  Top 0.254: J2.2 4.47,84.43 19.81,84.43 19.81,86.06 v36.07,102.31
  Bottom 0.254: v36.07,102.31 46.63,102.31 50.6,98.35 53.24,98.35 55.07,100.18 55.07,101.3 55.47,101.3 55.78,101.6 64.92,101.6 71.63,94.89 7.VCC
8-MISO  (via drill 0.51)
  Top 0.254: v84.63,40.54 87.99,43.89 89.92,43.89 8.D12
  Bottom 0.254: J10.1 6.2,34.44 78.54,34.44 v84.63,40.54
8-MOSI  (via drill 0.51)
  Top 0.254: v80.06,33.63 87.78,41.35 89.92,41.35 8.D11
  Bottom 0.254: J10.4 2.85,36.88 2.03,36.88 1.22,36.07 1.22,33.63 v80.06,33.63
8-RST  (via drill 0.51)
  Top 0.254: v65.23,36.27 63.6,37.9 63.6,57.81 68.89,63.09 73.15,63.09 73.15,62.99 74.37,61.77 74.68,61.77 8.RST
  Bottom 0.254: J10.5 5.69,40.03 6.2,40.03 9.65,36.58 21.13,36.58 21.84,35.87 64.82,35.87 v65.23,36.27
8-SCK  (via drill 0.51)
  Top 0.254: v78.23,35.36 86.06,43.18 86.06,44.7 87.78,46.43 89.92,46.43 8.D13
  Bottom 0.254: J10.3 7.42,36.07 20.93,36.07 21.64,35.36 v78.23,35.36
8-VCC  (via drill 0.51)
  Top 0.254: J10.2 v5.38,32.72 | v73.25,32.72 83.52,42.98 83.52,58.73 84.73,59.94 89.92,59.94 8.VCC
  Bottom 0.254: v5.38,32.72 v73.25,32.72
A0-0
  Top 0.254: 0.A0 53.34,116.13 50.7,116.13 50.7,116.43 49.48,117.65 49.48,119.38 50.8,120.7 53.34,120.7 0.A2
A0-1
  Top 0.254: 1.A0 71.63,116.13 68.99,116.13 68.99,116.43 67.77,117.65 67.77,119.38 69.09,120.7 71.63,120.7 1.A2
A0-2
  Top 0.254: 2.A0 89.92,116.13 90.63,116.13 90.63,116.53 91.85,117.75 91.85,119.48 90.22,121.11 89.92,121.11 2.A2
A0-3
  Top 0.254: 3.A0 53.34,82.6 50.7,82.6 50.7,82.91 49.48,84.12 49.48,85.85 50.8,87.17 53.34,87.17 3.A2
A0-4
  Top 0.254: 4.A0 71.63,49.07 68.99,49.07 68.99,49.38 67.77,50.6 67.77,52.32 69.09,53.65 71.63,53.65 4.A2
A0-5
  Top 0.254: 5.A0 53.34,49.07 50.7,49.07 50.7,49.38 49.48,50.6 49.48,52.32 50.8,53.65 53.34,53.65 5.A2
A0-6
  Top 0.254: 6.A0 89.92,82.6 90.63,82.6 90.63,83.01 91.85,84.23 91.85,85.95 90.22,87.58 89.92,87.58 6.A2
A0-7
  Top 0.254: 7.A0 71.63,82.6 68.99,82.6 68.99,82.91 67.77,84.12 67.77,85.85 69.09,87.17 71.63,87.17 7.A2
A1-0
  Top 0.254: 0.A1 53.34,118.67 54.66,119.99 54.66,122.23 53.34,123.55 0.A3
A1-1
  Bottom 0.254: 1.A1 71.63,118.67 72.95,119.99 72.95,123.04 72.85,123.04 72.24,123.65 71.63,123.65 1.A3
A1-2
  Bottom 0.254: 2.A1 89.92,118.67 91.85,120.6 91.85,123.65 89.92,123.65 2.A3
A1-3
  Top 0.254: 3.A1 53.34,85.14 54.66,86.46 54.66,88.7 53.34,90.02 3.A3
A1-4
  Top 0.254: 4.A1 71.63,51.61 72.95,52.93 72.95,55.17 71.63,56.49 4.A3
A1-5
  Bottom 0.254: 5.A1 53.34,51.61 54.66,52.93 54.66,55.98 54.56,55.98 53.95,56.59 53.34,56.59 5.A3
A1-6
  Bottom 0.254: 6.A1 89.92,85.14 91.85,87.07 91.85,90.12 89.92,90.12 6.A3
A1-7
  Top 0.254: 7.A1 71.63,85.14 72.95,86.46 72.95,88.7 71.63,90.02 7.A3
A4-0
  Bottom 0.254: 0.A4 49.07,122.43 40.95,130.56 38.81,130.56 38.1,131.27 0.RXI
A4-1
  Bottom 0.254: 1.A4 67.36,122.43 59.23,130.56 57.1,130.56 56.39,131.27 1.RXI
A4-2
  Bottom 0.254: 2.A4 85.65,122.43 77.52,130.56 75.39,130.56 74.68,131.27 2.RXI
A4-3
  Bottom 0.254: 3.A4 49.28,88.9 41.15,97.03 38.81,97.03 38.1,97.74 3.RXI
A4-4
  Bottom 0.254: 4.A4 67.36,55.37 59.23,63.5 57.1,63.5 56.39,64.21 4.RXI
A4-5
  Bottom 0.254: 5.A4 49.07,55.37 40.95,63.5 38.81,63.5 38.1,64.21 5.RXI
A4-6
  Bottom 0.254: 6.A4 85.65,88.9 77.52,97.03 75.39,97.03 74.68,97.74 6.RXI
A4-7
  Bottom 0.254: 7.A4 67.36,88.9 59.23,97.03 57.1,97.03 56.39,97.74 7.RXI
A5-0
  Bottom 0.254: 0.A5 49.07,124.97 40.95,133.1 38.81,133.1 38.1,133.81 0.TXO
A5-1
  Bottom 0.254: 1.A5 67.36,124.97 59.23,133.1 57.1,133.1 56.39,133.81 1.TXO
A5-2
  Bottom 0.254: 2.A5 85.65,124.97 77.52,133.1 75.39,133.1 74.68,133.81 2.TXO
A5-3
  Bottom 0.254: 3.A5 49.07,91.44 40.95,99.57 38.81,99.57 38.1,100.28 3.TXO
A5-4
  Bottom 0.254: 4.A5 67.36,57.91 59.23,66.04 57.1,66.04 56.39,66.75 4.TXO
A5-5  (via drill 0.51)
  Top 0.254: v53.54,64.01 50.8,61.27 5.A5
  Bottom 0.254: v53.54,64.01 53.24,64.31 43.79,64.31 41.76,66.34 38.51,66.34 38.1,66.75 5.TXO
A5-6
  Bottom 0.254: 6.A5 85.65,91.44 77.52,99.57 75.39,99.57 74.68,100.28 6.TXO
A5-7
  Bottom 0.254: 7.A5 66.55,91.44 62.69,95.3 61.87,95.3 61.87,96.93 59.23,99.57 57.1,99.57 56.39,100.28 7.TXO
D2-0
  Top 0.254: 0.D4 38.1,118.67 40.74,118.67 40.74,118.97 41.96,120.19 41.96,121.92 40.23,123.65 38.1,123.65 0.D2
D2-1
  Bottom 0.254: 1.D4 56.39,118.67 57.1,119.38 59.23,119.38 60.25,120.4 60.25,123.34 59.13,123.34 58.83,123.65 56.39,123.65 1.D2
D2-2
  Top 0.254: 2.D4 74.68,118.67 72.95,120.4 72.95,121.41 74.68,123.14 2.D2
D2-3
  Top 0.254: 3.D4 38.1,85.14 40.74,85.14 40.74,85.45 41.96,86.66 41.96,88.39 40.23,90.12 38.1,90.12 3.D2
D2-4
  Top 0.254: 4.D4 56.39,51.61 54.66,53.34 54.66,54.36 56.39,56.08 4.D2
D2-5
  Top 0.254: 5.D4 38.1,51.61 40.74,51.61 40.74,51.92 41.96,53.14 41.96,54.86 40.23,56.59 38.1,56.59 5.D2
D2-6
  Bottom 0.254: 6.D4 74.68,85.14 75.39,85.85 77.52,85.85 78.54,86.87 78.54,89.81 77.42,89.81 77.11,90.12 74.68,90.12 6.D2
D2-7
  Bottom 0.254: 7.D4 56.39,85.14 57.1,85.85 59.23,85.85 60.25,86.87 60.25,89.81 59.13,89.81 58.83,90.12 56.39,90.12 7.D2
D3-0
  Top 0.254: 0.D5 38.1,116.13 37.29,116.13 37.29,116.64 36.17,117.75 36.17,119.48 37.8,121.11 38.1,121.11 0.D3
D3-1
  Top 0.254: 1.D5 56.39,116.13 59.03,116.13 59.03,116.43 60.25,117.65 60.25,119.38 58.52,121.11 56.39,121.11 1.D3
D3-2
  Top 0.254: 2.D5 74.68,116.13 77.32,116.13 77.32,116.43 78.54,117.65 78.54,119.38 76.81,121.11 74.68,121.11 2.D3
D3-3
  Top 0.254: 3.D5 38.1,82.6 37.29,82.6 37.29,83.11 36.17,84.23 36.17,85.95 37.8,87.58 38.1,87.58 3.D3
D3-4
  Top 0.254: 4.D5 56.39,49.07 59.03,49.07 59.03,49.38 60.25,50.6 60.25,52.32 58.52,54.05 56.39,54.05 4.D3
D3-5
  Top 0.254: 5.D5 38.1,49.07 37.29,49.07 37.29,49.58 36.17,50.7 36.17,52.43 37.8,54.05 38.1,54.05 5.D3
D3-6
  Top 0.254: 6.D5 74.68,82.6 77.32,82.6 77.32,82.91 78.54,84.12 78.54,85.85 76.81,87.58 74.68,87.58 6.D3
D3-7
  Top 0.254: 7.D5 56.39,82.6 59.03,82.6 59.03,82.91 60.25,84.12 60.25,85.85 58.52,87.58 56.39,87.58 7.D3
D6-0
  Top 0.254: 0.D8 38.1,108.51 40.74,108.51 40.74,108.81 41.96,110.03 41.96,111.76 40.23,113.49 38.1,113.49 0.D6
  Bottom 0.254: 0.D10 53.34,105.97 52.93,106.38 49.68,106.38 47.65,108.41 38.1,108.41 0.D8
D6-1
  Top 0.254: 1.D8 56.39,108.51 59.03,108.51 59.03,108.81 60.25,110.03 60.25,111.76 58.52,113.49 56.39,113.49 1.D6
  Bottom 0.254: 1.D10 71.63,105.97 71.22,106.38 67.97,106.38 65.94,108.41 56.39,108.41 1.D8
D6-2
  Top 0.254: 2.D8 74.68,108.51 77.32,108.51 77.32,108.81 78.54,110.03 78.54,111.76 76.81,113.49 74.68,113.49 2.D6
  Bottom 0.254: 2.D10 89.92,105.97 89.51,106.38 86.26,106.38 84.23,108.41 74.68,108.41 2.D8
D6-3
  Top 0.254: 3.D8 38.1,74.98 40.74,74.98 40.74,75.29 41.96,76.5 41.96,78.23 40.23,79.96 38.1,79.96 3.D6
  Bottom 0.254: 3.D10 53.34,72.44 52.93,72.85 49.68,72.85 47.65,74.88 38.1,74.88 3.D8
D6-4
  Top 0.254: 4.D8 56.39,41.45 55.07,42.77 55.07,44.5 56.39,45.82 4.D6
  Bottom 0.254: 4.D10 71.63,38.91 70.92,39.62 68.58,39.62 66.45,41.76 59.13,41.76 58.83,41.45 56.39,41.45 4.D8
D6-5
  Top 0.254: 5.D8 38.1,41.45 37.29,41.45 37.29,41.96 36.17,43.08 36.17,44.81 37.8,46.43 38.1,46.43 5.D6
  Bottom 0.254: 5.D10 53.34,38.91 52.93,39.32 49.68,39.32 47.65,41.35 38.1,41.35 5.D8
D6-6
  Top 0.254: 6.D8 74.68,74.98 77.32,74.98 77.32,75.29 78.54,76.5 78.54,78.23 76.81,79.96 74.68,79.96 6.D6
  Bottom 0.254: 6.D10 89.92,72.44 89.51,72.85 86.26,72.85 84.23,74.88 74.68,74.88 6.D8
D6-7
  Top 0.254: 7.D8 56.39,74.98 59.03,74.98 59.03,75.29 60.25,76.5 60.25,78.23 58.52,79.96 56.39,79.96 7.D6
  Bottom 0.254: 7.D10 71.63,72.44 70.92,73.15 68.58,73.15 67.67,74.07 59.74,74.07 58.93,74.88 56.39,74.88 7.D8
D7-0
  Top 0.254: 0.D9 38.1,105.97 37.29,105.97 37.29,106.48 36.17,107.59 36.17,109.32 37.8,110.95 38.1,110.95 0.D7
D7-1
  Top 0.254: 1.D9 56.39,105.97 55.07,107.29 55.07,109.02 56.39,110.34 1.D7
D7-2
  Top 0.254: 2.D9 74.68,105.97 73.36,107.29 73.36,109.02 74.68,110.34 2.D7
D7-3
  Top 0.254: 3.D9 38.1,72.44 37.29,72.44 37.29,72.95 36.17,74.07 36.17,75.79 37.8,77.42 38.1,77.42 3.D7
D7-4
  Top 0.254: 4.D9 56.39,38.91 59.03,38.91 59.03,39.22 60.25,40.44 60.25,42.16 58.52,43.89 56.39,43.89 4.D7
D7-5
  Top 0.254: 5.D9 38.1,38.91 40.74,38.91 40.74,39.22 41.96,40.44 41.96,42.16 40.23,43.89 38.1,43.89 5.D7
D7-6
  Top 0.254: 6.D9 74.68,72.44 73.36,73.76 73.36,75.49 74.68,76.81 6.D7
D7-7
  Top 0.254: 7.D9 56.39,72.44 55.07,73.76 55.07,75.49 56.39,76.81 7.D7
DTR
  Top 0.254: S1.3 51.31,4.17 51.31,4.27 49.48,4.27 48.26,5.49 R1.1 48.26,5.59 46.74,7.11 46.74,64.82 51.21,69.29 52.02,69.29 5.DTR | 8.DTR 88.7,69.39 89.71,69.39 92.46,72.14 92.46,101.19 91.24,102.41 91.24,102.82 88.7,102.82 6.DTR 90.53,102.92 90.53,103.73 92.46,105.66 92.46,134.72 91.24,135.94 91.24,136.35 88.7,136.35 2.DTR
  Bottom 0.254: 0.DTR 52.43,136.04 69.49,136.04 69.8,136.35 70.31,136.35 1.DTR 70.41,136.45 73.56,136.45 73.76,136.65 88.39,136.65 2.DTR | 3.DTR 52.12,102.82 70.31,102.82 7.DTR 70.41,102.92 73.56,102.92 73.76,103.12 88.39,103.12 6.DTR | 5.DTR 52.43,69.7 69.49,69.7 69.8,69.39 70.31,69.39 4.DTR 70.31,69.49 88.49,69.49 8.DTR
GND  (via drill 0.51)
  other vias: 66.04,129.54
  pour Top (isolate 0.305): 0,0 0,154.94 109.22,154.94 109.22,0
  pour Bottom (isolate 0.305): 0,0 0,154.94 109.22,154.94 109.22,0
N$1
  Top 0.254: 8.D3 77.98,54.1 78.74,53.34 78.74,49.53 78.11,48.9 74.8,48.9 8.D5
N$2  (via drill 0.51)
  Top 0.254: v81.28,63.5 77.98,66.8 8.TXO
  Bottom 0.254: 8.A5 86.87,57.91 v81.28,63.5
N$9
  Top 0.254: 8.A0 89.92,49.07 90.63,49.07 90.63,49.48 91.85,50.7 91.85,52.43 90.22,54.05 89.92,54.05 8.A2
N$10
  Bottom 0.254: 8.A1 89.92,51.61 91.85,53.54 91.85,56.59 89.92,56.59 8.A3
N$11
  Bottom 0.254: 8.A4 86.67,56.08 84.53,56.08 76.4,64.21 74.68,64.21 8.RXI
N$13
  Bottom 0.254: 8.D2 74.68,56.59 75.39,55.88 77.52,55.88 78.54,54.86 78.54,51.92 77.42,51.92 77.11,51.61 74.68,51.61 8.D4
N$15
  Bottom 0.254: 78.54,43.18 77.52,42.16 75.39,42.16 74.68,41.45 8.D8 | 78.54,43.18 78.54,46.13 77.42,46.13 77.11,46.43 74.68,46.43 8.D6 | 8.D10 89.92,38.91 89.2,39.62 86.87,39.62 83.31,43.18 78.54,43.18
N$16
  Top 0.254: 8.D9 74.68,38.91 73.36,40.23 73.36,41.96 74.68,43.28 8.D7
RAW
  Top 0.254: F9.2 85.04,147.52 82.6,147.52 F5.2 82.5,147.52 80.06,147.52 F6.2 79.96,147.52 77.52,147.52 F7.2 77.42,147.52 74.98,147.52 F8.2 74.88,147.52 72.44,147.52 F4.2 72.34,147.52 69.9,147.52 F3.2 69.8,147.52 67.36,147.52 F2.2 67.26,147.52 64.82,147.52 F1.2 64.72,147.42 57.2,147.42 53.95,144.17 53.95,143.66 52.12,143.66 J1.PWR
RAW0
  Top 0.254: F1.1 64.72,144.58 54.05,133.91 53.34,133.91 0.RAW
RAW1
  Top 0.254: F2.1 67.36,144.58 68.28,143.66 68.28,135.74 70.1,133.91 71.63,133.91 1.RAW
RAW2  (via drill 0.51)
  Top 0.254: v76.5,135.74 76.5,137.97 69.9,144.58 F3.1
  Bottom 0.254: v76.5,135.74 76.61,135.84 85.45,135.84 87.38,133.91 89.92,133.91 2.RAW
RAW3
  Top 0.254: F4.1 72.34,144.68 71.12,144.68 71.12,145.29 70.92,145.49 66.04,145.49 66.04,143.97 60.76,138.68 60.76,105.66 57.4,102.31 55.27,102.31 53.34,100.38 3.RAW
RAW4
  Top 0.254: F5.1 82.5,144.58 80.97,143.05 80.97,74.07 75.69,68.78 73.56,68.78 71.63,66.85 4.RAW
RAW5
  Top 0.254: F6.1 80.06,144.58 80.47,144.17 80.47,101.09 78.44,99.06 73.05,99.06 73.05,98.96 71.12,97.03 67.67,97.03 67.67,95.4 60.76,88.49 60.76,72.14 57.4,68.78 55.27,68.78 53.34,66.85 5.RAW
RAW6  (via drill 0.51)
  Top 0.254: v79.55,101.4 79.55,142.55 77.52,144.58 F7.1
  Bottom 0.254: v79.55,101.4 80.57,100.38 89.92,100.38 6.RAW
RAW7
  Top 0.254: F8.1 74.98,144.58 77.42,142.14 77.42,135.84 79.05,134.21 79.05,105.66 75.69,102.31 73.56,102.31 71.63,100.38 7.RAW
RAW8
  Top 0.254: F9.1 85.04,144.58 83.52,143.05 83.52,71.73 88.39,66.85 89.92,66.85 8.RAW

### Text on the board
tPlace: 7V | 1 | 2 | 1 | 2 | 3 | 3 | 4 | 5 | 4 | 5 | 6 | 6 | 7 | 8 | 7 | 8 | 9 | 9 | DTR-reset test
